(* Logix 5000 project; controller Motion_Axis_AOIs_AMCI_RSLogix_V31 vendor 1 type 14 code 108 rev 31.11; software revision 31.02; part 3 of 7 *)

ADD_ON_INSTRUCTION AMCI_MA_SD_SMD_Linear_Follower   (* revision 5.0, vendor AMCI, ExecuteEnableInFalse *)
// Linear Axis Follower for SD and SMD devices.   Will not work with SV integrated servo devices.
// Help:
// MOTION AXIS SD & SMD LINEAR FOLLOWER
// These AOIs will only work with the SD and SMD motion devices.  The SV motion devices have their own follower AOIs.
// AXIS INPUT DATA:  Input data from AMCI motion device.   Uses the AMCI_Motion_Axis_Input_Data User Defined Data Type.
// AXIS OUTPUT DATA; Output data from the AOI to the AMCI motion device.   Uses the AMCI_Motion_Axis_Output_Data User Defined Data Type.
// FOLLOWER POSITION: REAL DATA TYPE position directly from the motion axis.
// FOLLOWER VELOCITY: REAL DATA TYPE velocity directly from the motion axis.
// ACCELERATION & DECELERATION: An actual value or an INT DATA TYPE.  Larger acceleration and
//                                                             deceleration values will cause the motion device to more quickly react
//                                                              changes in the source position and velocity values.
// PROPORTIONAL COEFFICIENT:  A value of 1 or 2 is recommended
// NETWORK DELAY: A value of zero, or 1 to the RPI time, will work in most applications.
// EN (Enable) Set when rung is true, Reset when rung is false
// DN (Done) Set when command is sent to the motion device.  Reset when the rung is false.
// ER (Error) Set when a command or input error failed to clear.  Reset when the rung is false.
// IP (In Process) Set when follower command is active, even if motion is not occurring.   Reset when the rung
//                         goes false.
VAR_IN_OUT
   Axis_Input_Data : AMCI_Motion_Axis_Input_Data; {required}
   Axis_Output_Data : AMCI_Motion_Axis_Output_Data; {required}
END_VAR
VAR_INPUT
   _0_for_Normal_1_for_Continuous : BOOL;
   Follower_Position : REAL; {required}
   Follower_Velocity : REAL; {required}
   Acceleration : INT; {required}
   Deceleration : INT; {required}
   Proportional_Coefficient : INT; {required}
   Network_delay : INT; {required}
END_VAR
VAR_OUTPUT
   EN : BOOL; {visible}
   ER : BOOL; {visible}
   DN : BOOL; {visible}
   IP : BOOL; {visible}
END_VAR
VAR
   command_data_block : INT[10];
        [2]   // Upper Target Position
        [4]   // Upper Programmed Speed
        [1]   // Command Bits LSW
        [5]   // Lower Programmed Speed
        [0]   // Command Bits MSW
        [3]   // Lower Target Position
   axis_follower_position : DINT;
   axis_follower_velocity : DINT;
END_VAR

ROUTINE EnableInFalse   (* ladder *)
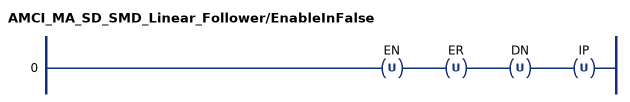
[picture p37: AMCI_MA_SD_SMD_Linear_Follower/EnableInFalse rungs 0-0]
   0: OTU(EN)OTU(ER)OTU(DN)OTU(IP);
END_ROUTINE

ROUTINE Logic   (* ladder *)
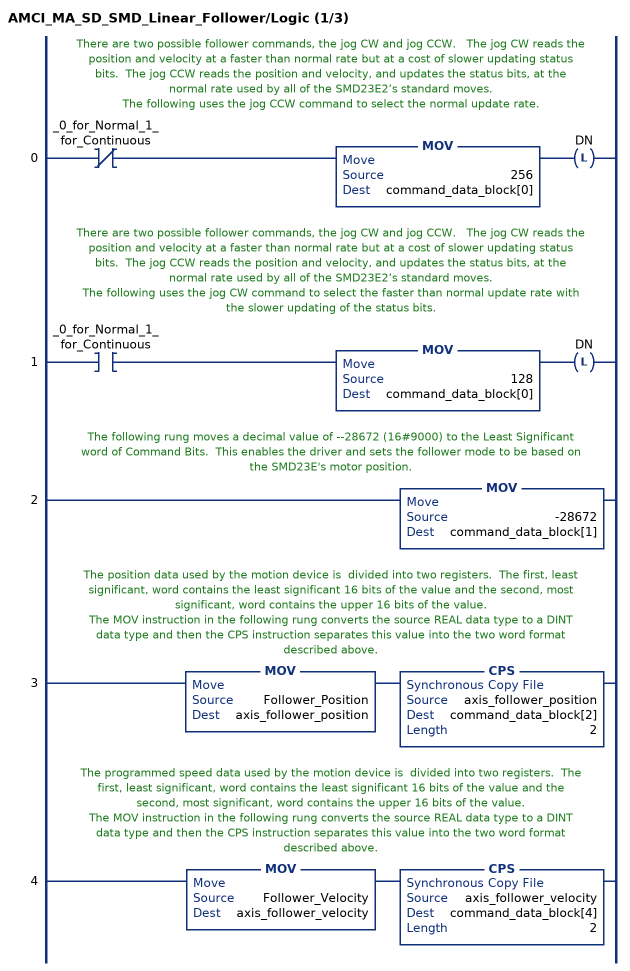
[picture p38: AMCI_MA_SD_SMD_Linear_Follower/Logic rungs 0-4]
   // There are two possible follower commands, the jog CW and jog CCW.   The jog CW reads the position and velocity at a faster than normal rate but at a cost of slower updating status bits.  The jog CCW reads the position and velocity, and updates the status bits, at the normal rate used by all of the SMD23E2’s standard moves.
   // The following uses the jog CCW command to select the normal update rate.
   0: XIO(_0_for_Normal_1_for_Continuous)MOV(256,command_data_block[0])OTL(DN);
   // There are two possible follower commands, the jog CW and jog CCW.   The jog CW reads the position and velocity at a faster than normal rate but at a cost of slower updating status bits.  The jog CCW reads the position and velocity, and updates the status bits, at the normal rate used by all of the SMD23E2’s standard moves.
   // The following uses the jog CW command to select the faster than normal update rate with the slower updating of the status bits.
   1: XIC(_0_for_Normal_1_for_Continuous)MOV(128,command_data_block[0])OTL(DN);
   // The following rung moves a decimal value of --28672 (16#9000) to the Least Significant word of Command Bits.  This enables the driver and sets the follower mode to be based on the SMD23E's motor position.
   2: MOV(-28672,command_data_block[1]);
   // The position data used by the motion device is  divided into two registers.  The first, least significant, word contains the least significant 16 bits of the value and the second, most significant, word contains the upper 16 bits of the value.
   // The MOV instruction in the following rung converts the source REAL data type to a DINT data type and then the CPS instruction separates this value into the two word format described above.
   3: MOV(Follower_Position,axis_follower_position)CPS(axis_follower_position,command_data_block[2],2);
   // The programmed speed data used by the motion device is  divided into two registers.  The first, least significant, word contains the least significant 16 bits of the value and the second, most significant, word contains the upper 16 bits of the value.
   // The MOV instruction in the following rung converts the source REAL data type to a DINT data type and then the CPS instruction separates this value into the two word format described above.
   4: MOV(Follower_Velocity,axis_follower_velocity)CPS(axis_follower_velocity,command_data_block[4],2);
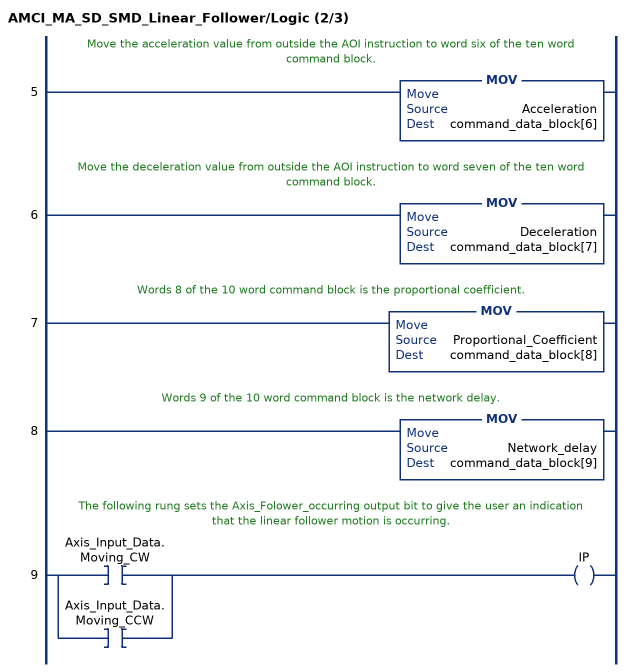
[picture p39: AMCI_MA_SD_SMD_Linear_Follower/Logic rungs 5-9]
   // Move the acceleration value from outside the AOI instruction to word six of the ten word command block.
   5: MOV(Acceleration,command_data_block[6]);
   // Move the deceleration value from outside the AOI instruction to word seven of the ten word command block.
   6: MOV(Deceleration,command_data_block[7]);
   // Words 8 of the 10 word command block is the proportional coefficient.
   7: MOV(Proportional_Coefficient,command_data_block[8]);
   // Words 9 of the 10 word command block is the network delay.
   8: MOV(Network_delay,command_data_block[9]);
   // The following rung sets the Axis_Folower_occurring output bit to give the user an indication that the linear follower motion is occurring.
   9: [XIC(Axis_Input_Data.Moving_CW) ,XIC(Axis_Input_Data.Moving_CCW) ]OTE(IP);
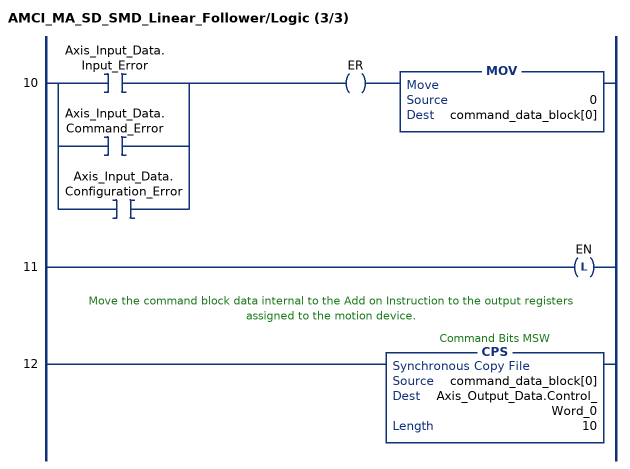
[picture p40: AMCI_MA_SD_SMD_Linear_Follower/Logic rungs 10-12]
   10: [XIC(Axis_Input_Data.Input_Error) ,XIC(Axis_Input_Data.Command_Error) ,XIC(Axis_Input_Data.Configuration_Error) ]OTE(ER)MOV(0,command_data_block[0]);
   11: OTL(EN);
   // Move the command block data internal to the Add on Instruction to the output registers assigned to the motion device.
   12: CPS(command_data_block[0],Axis_Output_Data.Control_Word_0,10);
END_ROUTINE
END_ADD_ON_INSTRUCTION

ADD_ON_INSTRUCTION AMCI_MA_SD_SMD_Linear_Follower_CIPSYNC   (* revision 1.0, vendor AMCI, ExecuteEnableInFalse *)
// Linear Axis Follower for SD and SMD devices.   Will not work with SV integrated servo devices.
// Revision note:
// 8/8/24.  Added timesync functionality to a previously existing AOI.  Also added logic to preset the motor position to the master axis position when the rung with the AOI becomes true, or if the master axis position changes when motion is not occurring.
// Help:
// MOTION AXIS SD & SMD LINEAR FOLLOWER
// These AOIs will only work with the SD and SMD motion devices.  The SV motion devices have their own follower AOIs.
// AXIS INPUT DATA:  Input data from AMCI motion device.   Uses the AMCI_Motion_Axis_Input_Data User Defined Data Type.
// AXIS OUTPUT DATA; Output data from the AOI to the AMCI motion device.   Uses the AMCI_Motion_Axis_Output_Data User Defined Data Type.
// FOLLOWER POSITION: REAL DATA TYPE position directly from the motion axis.
// FOLLOWER VELOCITY: REAL DATA TYPE velocity directly from the motion axis.
// ACCELERATION & DECELERATION: An actual value or an INT DATA TYPE.  Larger acceleration and
//                                                             deceleration values will cause the motion device to more quickly react
//                                                              changes in the source position and velocity values.
// PROPORTIONAL COEFFICIENT:  A value of 1 or 2 is recommended
// NETWORK DELAY: A value of zero, or 1 to the RPI time, will work in most applications.
// RPI_TIME: The RPI time used when adding the AMCI Motion device to the network.   8ms is the default.
//                    Used to control how long the preset motor command is sent to the device when the rung with the
//                    AOI transitions from false to true.
// TIMESYNC: The PLC's time value used to more closely synchronize the motion data from the PLC's master
//                     axis with the output of the AMCI motion device.
// EN (Enable) Set when rung is true, Reset when rung is false
// DN (Done) Set when command is sent to the motion device.  Reset when the rung is false.
// ER (Error) Set when a command or input error failed to clear.  Reset when the rung is false.
// IP (In Process) Set when follower command is active, even if motion is not occurring.   Reset when the rung
//                         goes false.
VAR_IN_OUT
   Axis_Input_Data : AMCI_Motion_Axis_Input_Data; {required}
   Axis_Output_Data : AMCI_Motion_Axis_Output_Data; {required}
END_VAR
VAR_INPUT
   Current_System_Time : DINT; {required}
   _0_for_Normal_1_for_Continuous : BOOL;
   Master_Axis_Position : REAL; {required}
   Master_Axis_Velocity : REAL; {required}
   Acceleration : INT; {required}
   Deceleration : INT; {required}
   Proportional_Coefficient : INT; {required}
   RPI_time_in_ms : DINT; {required}
END_VAR
VAR_OUTPUT
   EN : BOOL; {visible}
   ER : BOOL; {visible}
   DN : BOOL; {visible}
   IP : BOOL; {visible}
END_VAR
VAR
   command_data_block : INT[10];
        [1]   // Command Bits LSW
        [3]   // Lower Target Position
        [5]   // Lower Programmed Speed
        [0]   // Command Bits MSW
        [2]   // Upper Target Position
        [4]   // Upper Programmed Speed
   axis_follower_position : DINT;
   axis_follower_velocity : DINT;
   Preset_Motor_Position_timer_dynanic : TIMER; {access None}
   preset_one_shot : BOOL; {access None}
   RPI_div_1000 : REAL; {access None}
   difference_scan_position : DINT; {access None}
   last_scan_position : DINT; {access None}
   position_difference : DINT; {access None}
   position_last_scan_linear_SMD : DINT; {access None}
END_VAR

ROUTINE EnableInFalse   (* ladder *)
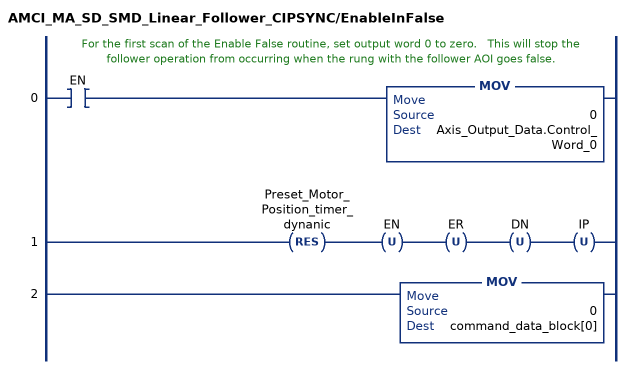
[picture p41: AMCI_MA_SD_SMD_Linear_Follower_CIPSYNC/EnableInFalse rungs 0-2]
   // For the first scan of the Enable False routine, set output word 0 to zero.   This will stop the follower operation from occurring when the rung with the follower AOI goes false.
   0: XIC(EN)MOV(0,Axis_Output_Data.Control_Word_0);
   1: RES(Preset_Motor_Position_timer_dynanic)OTU(EN)OTU(ER)OTU(DN)OTU(IP);
   2: MOV(0,command_data_block[0]);
END_ROUTINE

ROUTINE Logic   (* ladder *)
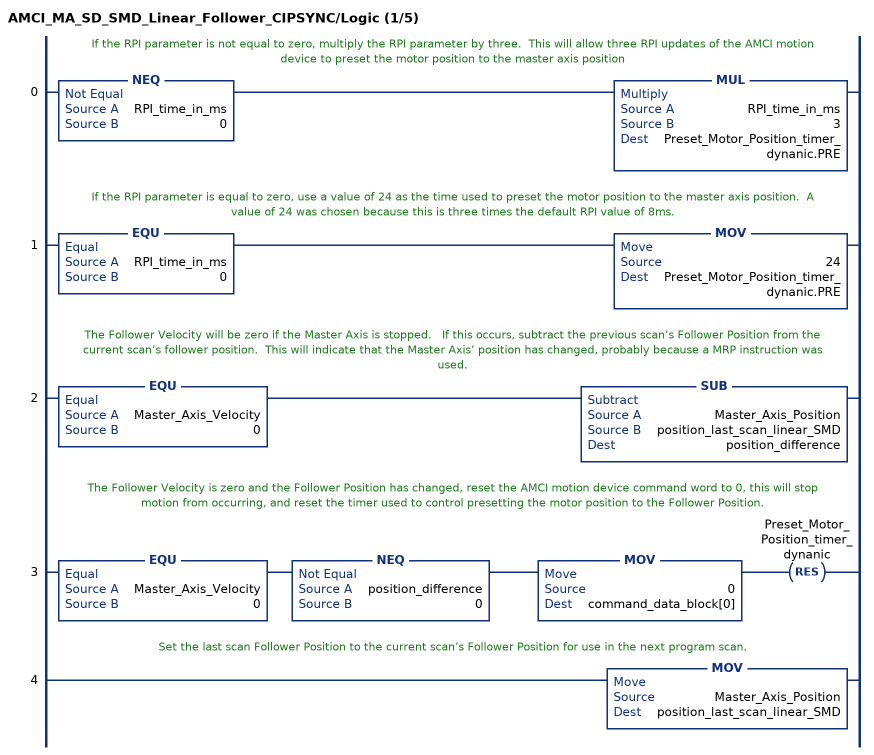
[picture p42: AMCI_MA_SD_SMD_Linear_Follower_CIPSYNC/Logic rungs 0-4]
   // If the RPI parameter is not equal to zero, multiply the RPI parameter by three.  This will allow three RPI updates of the AMCI motion device to preset the motor position to the master axis position
   0: NEQ(RPI_time_in_ms,0)MUL(RPI_time_in_ms,3,Preset_Motor_Position_timer_dynanic.PRE);
   // If the RPI parameter is equal to zero, use a value of 24 as the time used to preset the motor position to the master axis position.  A value of 24 was chosen because this is three times the default RPI value of 8ms.
   1: EQU(RPI_time_in_ms,0)MOV(24,Preset_Motor_Position_timer_dynanic.PRE);
   // The Follower Velocity will be zero if the Master Axis is stopped.   If this occurs, subtract the previous scan’s Follower Position from the current scan’s follower position.  This will indicate that the Master Axis’ position has changed, probably because a MRP instruction was used.
   2: EQU(Master_Axis_Velocity,0)SUB(Master_Axis_Position,position_last_scan_linear_SMD,position_difference);
   // The Follower Velocity is zero and the Follower Position has changed, reset the AMCI motion device command word to 0, this will stop motion from occurring, and reset the timer used to control presetting the motor position to the Follower Position.
   3: EQU(Master_Axis_Velocity,0)NEQ(position_difference,0)MOV(0,command_data_block[0])RES(Preset_Motor_Position_timer_dynanic);
   // Set the last scan Follower Position to the current scan’s Follower Position for use in the next program scan.
   4: MOV(Master_Axis_Position,position_last_scan_linear_SMD);
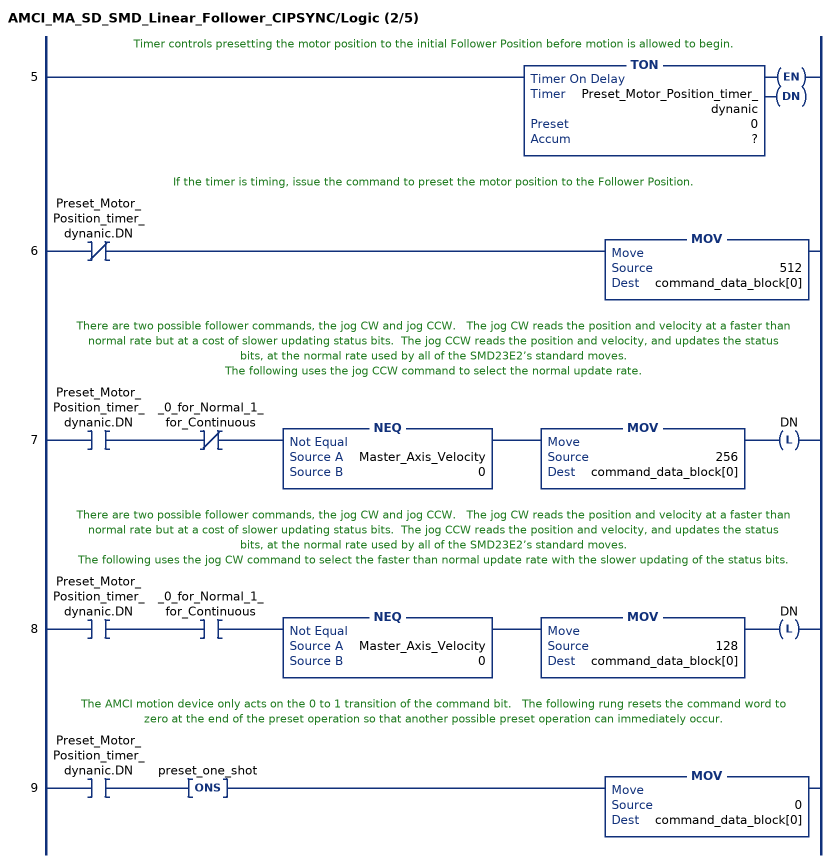
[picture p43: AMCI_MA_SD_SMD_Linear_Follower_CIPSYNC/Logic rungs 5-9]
   // Timer controls presetting the motor position to the initial Follower Position before motion is allowed to begin.
   5: TON(Preset_Motor_Position_timer_dynanic,?,?);
   // If the timer is timing, issue the command to preset the motor position to the Follower Position.
   6: XIO(Preset_Motor_Position_timer_dynanic.DN)MOV(512,command_data_block[0]);
   // There are two possible follower commands, the jog CW and jog CCW.   The jog CW reads the position and velocity at a faster than normal rate but at a cost of slower updating status bits.  The jog CCW reads the position and velocity, and updates the status bits, at the normal rate used by all of the SMD23E2’s standard moves.
   // The following uses the jog CCW command to select the normal update rate.
   7: XIC(Preset_Motor_Position_timer_dynanic.DN)XIO(_0_for_Normal_1_for_Continuous)NEQ(Master_Axis_Velocity,0)MOV(256,command_data_block[0])OTL(DN);
   // There are two possible follower commands, the jog CW and jog CCW.   The jog CW reads the position and velocity at a faster than normal rate but at a cost of slower updating status bits.  The jog CCW reads the position and velocity, and updates the status bits, at the normal rate used by all of the SMD23E2’s standard moves.
   // The following uses the jog CW command to select the faster than normal update rate with the slower updating of the status bits.
   8: XIC(Preset_Motor_Position_timer_dynanic.DN)XIC(_0_for_Normal_1_for_Continuous)NEQ(Master_Axis_Velocity,0)MOV(128,command_data_block[0])OTL(DN);
   // The AMCI motion device only acts on the 0 to 1 transition of the command bit.   The following rung resets the command word to zero at the end of the preset operation so that another possible preset operation can immediately occur.
   9: XIC(Preset_Motor_Position_timer_dynanic.DN)ONS(preset_one_shot)MOV(0,command_data_block[0]);
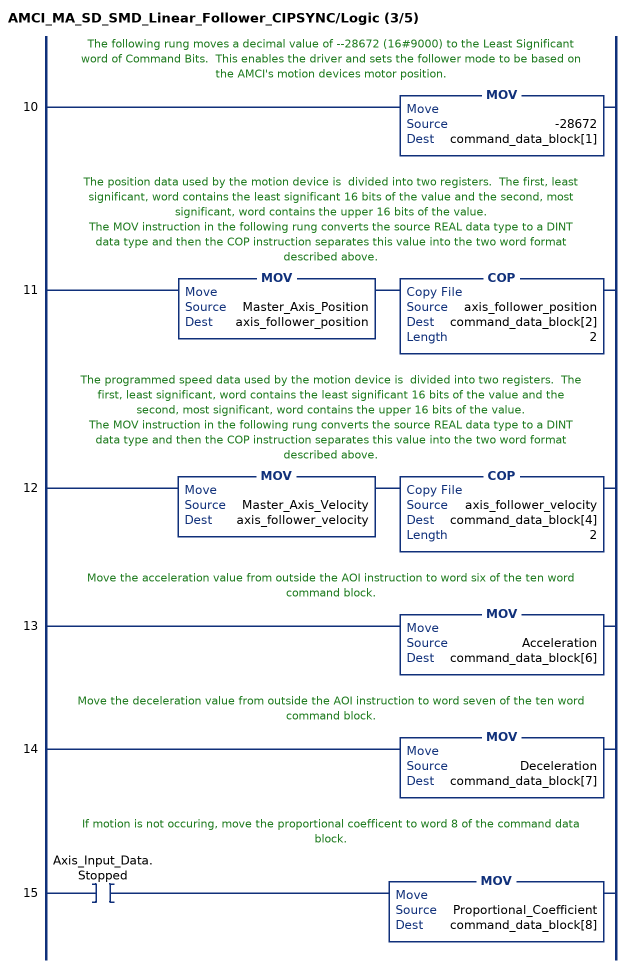
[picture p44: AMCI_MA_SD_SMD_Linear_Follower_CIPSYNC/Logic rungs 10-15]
   // The following rung moves a decimal value of --28672 (16#9000) to the Least Significant word of Command Bits.  This enables the driver and sets the follower mode to be based on the AMCI's motion devices motor position.
   10: MOV(-28672,command_data_block[1]);
   // The position data used by the motion device is  divided into two registers.  The first, least significant, word contains the least significant 16 bits of the value and the second, most significant, word contains the upper 16 bits of the value.
   // The MOV instruction in the following rung converts the source REAL data type to a DINT data type and then the COP instruction separates this value into the two word format described above.
   11: MOV(Master_Axis_Position,axis_follower_position)COP(axis_follower_position,command_data_block[2],2);
   // The programmed speed data used by the motion device is  divided into two registers.  The first, least significant, word contains the least significant 16 bits of the value and the second, most significant, word contains the upper 16 bits of the value.
   // The MOV instruction in the following rung converts the source REAL data type to a DINT data type and then the COP instruction separates this value into the two word format described above.
   12: MOV(Master_Axis_Velocity,axis_follower_velocity)COP(axis_follower_velocity,command_data_block[4],2);
   // Move the acceleration value from outside the AOI instruction to word six of the ten word command block.
   13: MOV(Acceleration,command_data_block[6]);
   // Move the deceleration value from outside the AOI instruction to word seven of the ten word command block.
   14: MOV(Deceleration,command_data_block[7]);
   // If motion is not occuring, move the proportional coefficent to word 8 of the command data block.
   15: XIC(Axis_Input_Data.Stopped)MOV(Proportional_Coefficient,command_data_block[8]);
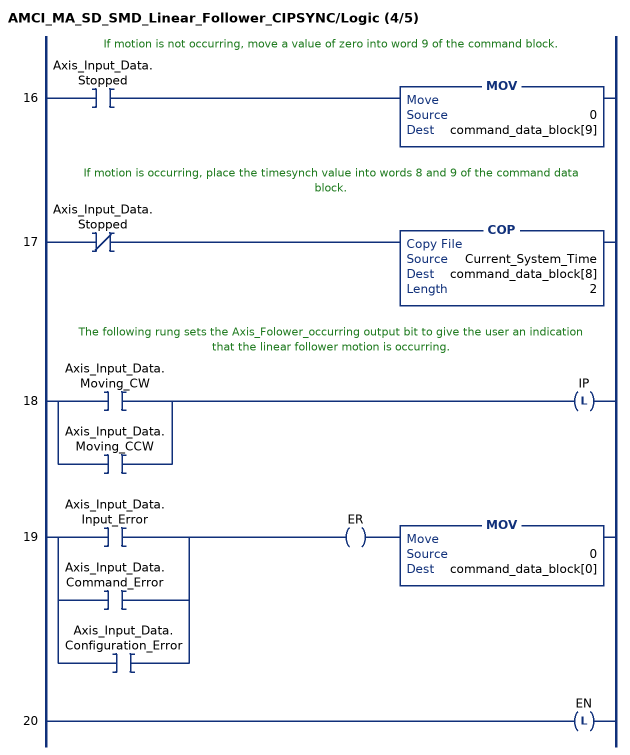
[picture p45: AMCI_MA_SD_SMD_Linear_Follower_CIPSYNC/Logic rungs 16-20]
   // If motion is not occurring, move a value of zero into word 9 of the command block.
   16: XIC(Axis_Input_Data.Stopped)MOV(0,command_data_block[9]);
   // If motion is occurring, place the timesynch value into words 8 and 9 of the command data block.
   17: XIO(Axis_Input_Data.Stopped)COP(Current_System_Time,command_data_block[8],2);
   // The following rung sets the Axis_Folower_occurring output bit to give the user an indication that the linear follower motion is occurring.
   18: [XIC(Axis_Input_Data.Moving_CW) ,XIC(Axis_Input_Data.Moving_CCW) ]OTL(IP);
   19: [XIC(Axis_Input_Data.Input_Error) ,XIC(Axis_Input_Data.Command_Error) ,XIC(Axis_Input_Data.Configuration_Error) ]OTE(ER)MOV(0,command_data_block[0]);
   20: OTL(EN);
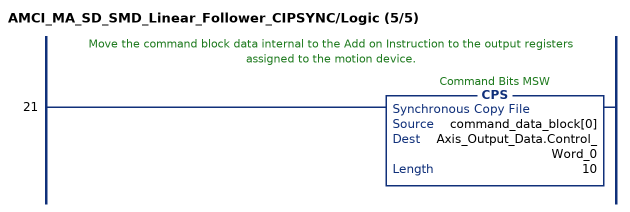
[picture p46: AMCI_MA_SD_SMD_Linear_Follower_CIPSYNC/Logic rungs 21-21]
   // Move the command block data internal to the Add on Instruction to the output registers assigned to the motion device.
   21: CPS(command_data_block[0],Axis_Output_Data.Control_Word_0,10);
END_ROUTINE
END_ADD_ON_INSTRUCTION

ADD_ON_INSTRUCTION AMCI_MA_SV_Circular_Follower   (* revision 1.1, vendor AMCI, ExecuteEnableInFalse *)
// Only for SVXXXE2 motion devices.
// Revision note:
// Version 1.1:  Corrected mistake in the text on the Help Tab.   Also limited the velocity to +/-1,048,575 steps / sec.
// Help:
// MOTION AXIS SV CIRCULAR FOLLOWER
// These AOIs will only work with the SV motion devices.  The SMD and SD  motion devices have their own follower AOIs.
// AXIS INPUT DATA:  Input data from AMCI motion device.   Uses the AMCI_Motion_Axis_Input_Data User Defined Data Type.
// AXIS OUTPUT DATA; Output data from the AOI to the AMCI motion device.   Uses the AMCI_Motion_Axis_Output_Data User Defined Data Type.
// FOLLOWER POSITION: REAL DATA TYPE position directly from the motion axis.
// FOLLOWER VELOCITY: REAL DATA TYPE velocity directly from the motion axis.
// FOLLOWER ACCELERATION: REAL DATA TYPE acceleration directly from the motion axis.
// RAMP ACCELERATION: An actual value or INT value used to transition from no motion to motion.   Once
//                                          motion is occurring, the follower acceleration will be used.  Range of 0 to 15,999.
// DECELERATION: An actual value or INT value used to transition from motion to no motion.   Range of 0 to
//                              15,999.
// CONVERSION CONSTANT: Converts revolutions and revolutions / sec  from the motion axis to the step and
//                                               steps / sec used by the motion axis.
// POSITION UNWIND: Must be set to the Unwind Value of the motion axis and defines the point at which the
//                                    position data will transition from its maximum to its minimum value.    The Position
//                                    Unwind Value MUST BE IN THE RANGE OF 21 TO 65535.
// EN (Enable) Set when rung is true, Reset when rung is false
// DN (Done) Set when command is sent to the motion device.  Reset when the rung is false.
// ER (Error) Set when a command or input error failed to clear.  Reset when the rung is false.
// IP (In Process) Set when motion is occurring.   Reset when the rung goes false.
VAR_IN_OUT
   Axis_Input_Data : AMCI_Motion_Axis_Input_Data; {required}
   Axis_Output_Data : AMCI_Motion_Axis_Output_Data; {required}
END_VAR
VAR_INPUT
   Follower_Position : REAL; {required}
   Follower_Velocity : REAL; {required}
   Follower_Acceleration : REAL; {required}
   Ramp_Acceleration : INT; {required}
   Deceleration : INT; {required}
   Conversion_Constant : REAL; {required}
   Position_Unwind : DINT; {required}
   Maximum_Move_Torque : INT;
END_VAR
VAR_OUTPUT
   EN : BOOL; {visible}
   ER : BOOL; {visible}
   DN : BOOL; {access Read Only, visible}
   IP : BOOL; {access Read Only, visible}
END_VAR
VAR
   command_data_block : INT[10];
        [8]   // Unwind value when stopped, Maximum Move Torque when motion occurring
        [2]   // Upper Target Position
        [4]   // Upper Programmed Speed
        [1]   // Command Bits LSW
        [3]   // Lower Target Position
        [5]   // Lower Programmed Speed
        [0]   // Command Bits MSW
   axis_follower_position : DINT;
   axis_follower_velocity : DINT;
   axis_follower_acceleration : DINT; {access None}
END_VAR

ROUTINE EnableInFalse   (* ladder *)
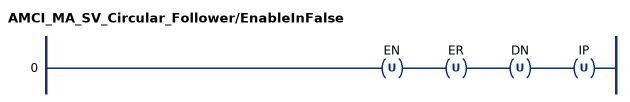
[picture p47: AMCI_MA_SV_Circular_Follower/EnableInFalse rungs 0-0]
   0: OTU(EN)OTU(ER)OTU(DN)OTU(IP);
END_ROUTINE

ROUTINE Logic   (* ladder *)
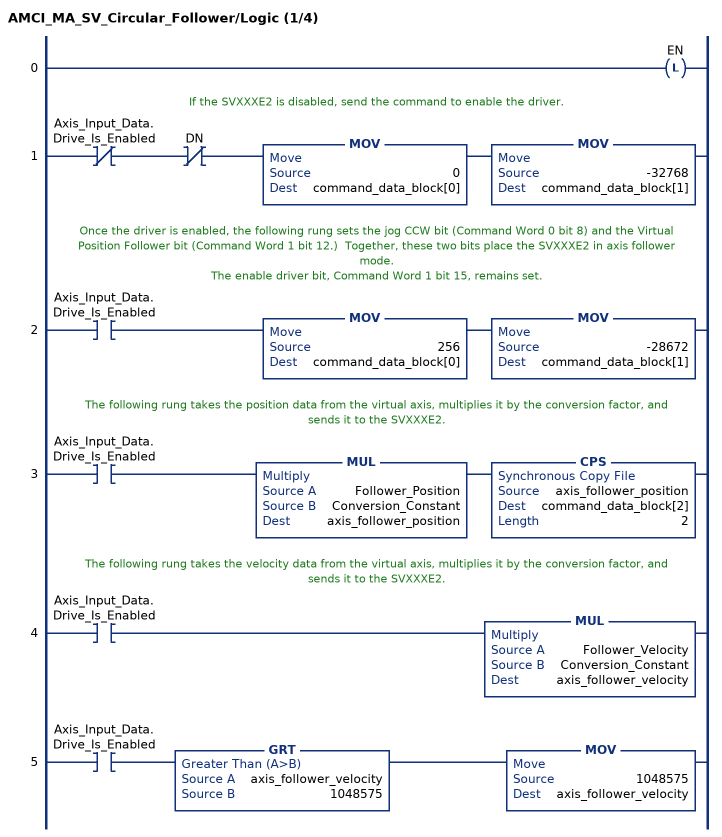
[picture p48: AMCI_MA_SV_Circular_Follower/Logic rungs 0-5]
   0: OTL(EN);
   // If the SVXXXE2 is disabled, send the command to enable the driver.
   1: XIO(Axis_Input_Data.Drive_Is_Enabled)XIO(DN)MOV(0,command_data_block[0])MOV(-32768,command_data_block[1]);
   // Once the driver is enabled, the following rung sets the jog CCW bit (Command Word 0 bit 8) and the Virtual Position Follower bit (Command Word 1 bit 12.)  Together, these two bits place the SVXXXE2 in axis follower mode.
   // The enable driver bit, Command Word 1 bit 15, remains set.
   2: XIC(Axis_Input_Data.Drive_Is_Enabled)MOV(256,command_data_block[0])MOV(-28672,command_data_block[1]);
   // The following rung takes the position data from the virtual axis, multiplies it by the conversion factor, and sends it to the SVXXXE2.
   3: XIC(Axis_Input_Data.Drive_Is_Enabled)MUL(Follower_Position,Conversion_Constant,axis_follower_position)CPS(axis_follower_position,command_data_block[2],2);
   // The following rung takes the velocity data from the virtual axis, multiplies it by the conversion factor, and sends it to the SVXXXE2.
   4: XIC(Axis_Input_Data.Drive_Is_Enabled)MUL(Follower_Velocity,Conversion_Constant,axis_follower_velocity);
   5: XIC(Axis_Input_Data.Drive_Is_Enabled)GRT(axis_follower_velocity,1048575)MOV(1048575,axis_follower_velocity);
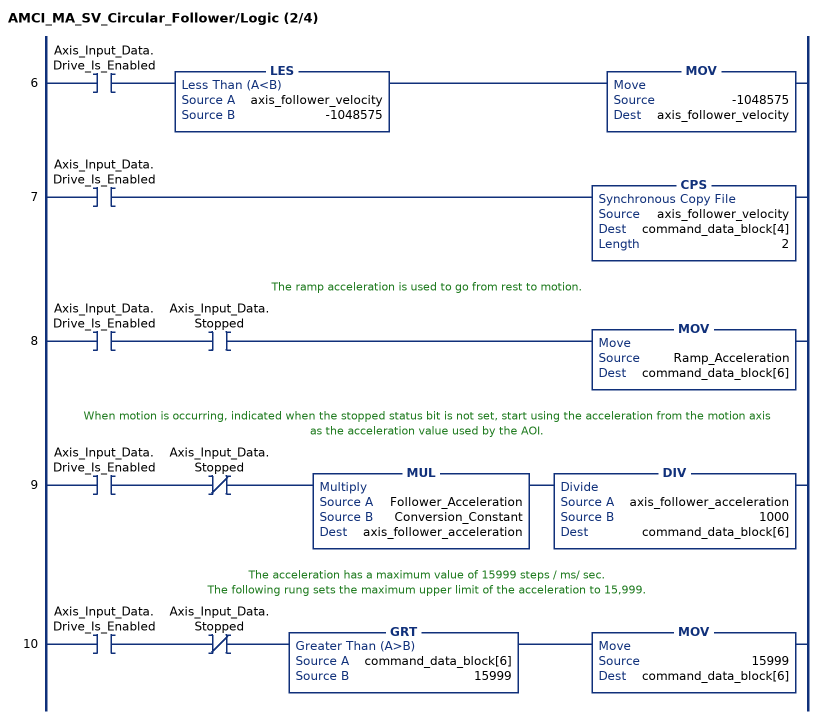
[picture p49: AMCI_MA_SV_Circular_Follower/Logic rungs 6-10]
   6: XIC(Axis_Input_Data.Drive_Is_Enabled)LES(axis_follower_velocity,-1048575)MOV(-1048575,axis_follower_velocity);
   7: XIC(Axis_Input_Data.Drive_Is_Enabled)CPS(axis_follower_velocity,command_data_block[4],2);
   // The ramp acceleration is used to go from rest to motion.
   8: XIC(Axis_Input_Data.Drive_Is_Enabled)XIC(Axis_Input_Data.Stopped)MOV(Ramp_Acceleration,command_data_block[6]);
   // When motion is occurring, indicated when the stopped status bit is not set, start using the acceleration from the motion axis as the acceleration value used by the AOI.
   9: XIC(Axis_Input_Data.Drive_Is_Enabled)XIO(Axis_Input_Data.Stopped)MUL(Follower_Acceleration,Conversion_Constant,axis_follower_acceleration)DIV(axis_follower_acceleration,1000,command_data_block[6]);
   // The acceleration has a maximum value of 15999 steps / ms/ sec.
   // The following rung sets the maximum upper limit of the acceleration to 15,999.
   10: XIC(Axis_Input_Data.Drive_Is_Enabled)XIO(Axis_Input_Data.Stopped)GRT(command_data_block[6],15999)MOV(15999,command_data_block[6]);
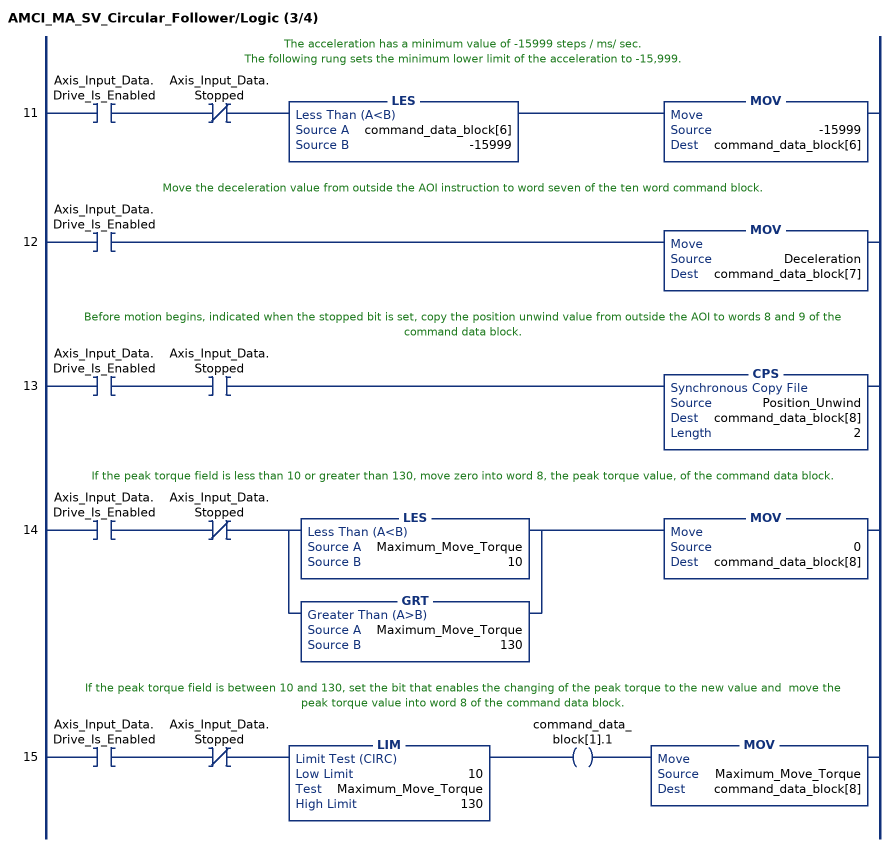
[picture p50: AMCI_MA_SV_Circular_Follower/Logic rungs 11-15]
   // The acceleration has a minimum value of -15999 steps / ms/ sec.
   // The following rung sets the minimum lower limit of the acceleration to -15,999.
   11: XIC(Axis_Input_Data.Drive_Is_Enabled)XIO(Axis_Input_Data.Stopped)LES(command_data_block[6],-15999)MOV(-15999,command_data_block[6]);
   // Move the deceleration value from outside the AOI instruction to word seven of the ten word command block.
   12: XIC(Axis_Input_Data.Drive_Is_Enabled)MOV(Deceleration,command_data_block[7]);
   // Before motion begins, indicated when the stopped bit is set, copy the position unwind value from outside the AOI to words 8 and 9 of the command data block.
   13: XIC(Axis_Input_Data.Drive_Is_Enabled)XIC(Axis_Input_Data.Stopped)CPS(Position_Unwind,command_data_block[8],2);
   // If the peak torque field is less than 10 or greater than 130, move zero into word 8, the peak torque value, of the command data block.
   14: XIC(Axis_Input_Data.Drive_Is_Enabled)XIO(Axis_Input_Data.Stopped)[LES(Maximum_Move_Torque,10) ,GRT(Maximum_Move_Torque,130) ]MOV(0,command_data_block[8]);
   // If the peak torque field is between 10 and 130, set the bit that enables the changing of the peak torque to the new value and  move the peak torque value into word 8 of the command data block.
   15: XIC(Axis_Input_Data.Drive_Is_Enabled)XIO(Axis_Input_Data.Stopped)LIM(10,Maximum_Move_Torque,130)OTE(command_data_block[1].1)MOV(Maximum_Move_Torque,command_data_block[8]);
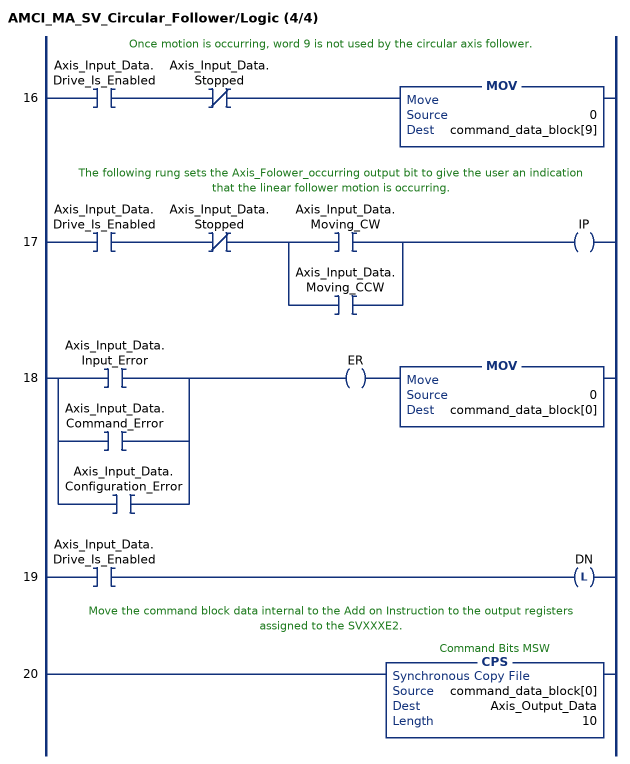
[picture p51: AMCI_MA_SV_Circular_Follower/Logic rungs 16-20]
   // Once motion is occurring, word 9 is not used by the circular axis follower.
   16: XIC(Axis_Input_Data.Drive_Is_Enabled)XIO(Axis_Input_Data.Stopped)MOV(0,command_data_block[9]);
   // The following rung sets the Axis_Folower_occurring output bit to give the user an indication that the linear follower motion is occurring.
   17: XIC(Axis_Input_Data.Drive_Is_Enabled)XIO(Axis_Input_Data.Stopped)[XIC(Axis_Input_Data.Moving_CW) ,XIC(Axis_Input_Data.Moving_CCW) ]OTE(IP);
   18: [XIC(Axis_Input_Data.Input_Error) ,XIC(Axis_Input_Data.Command_Error) ,XIC(Axis_Input_Data.Configuration_Error) ]OTE(ER)MOV(0,command_data_block[0]);
   19: XIC(Axis_Input_Data.Drive_Is_Enabled)OTL(DN);
   // Move the command block data internal to the Add on Instruction to the output registers assigned to the SVXXXE2.
   20: CPS(command_data_block[0],Axis_Output_Data,10);
END_ROUTINE
END_ADD_ON_INSTRUCTION

ADD_ON_INSTRUCTION AMCI_MA_SV_Circular_Follower_CIPSync   (* revision 1.0, vendor AMCI, ExecuteEnableInFalse *)
// Only for SVXXXE2 motion devices.
// Revision note:
// 8/8/24.  Added CIPSync functionality to a previously existing AOI.  The abiltiy to change the maximum move torque is no longer available because the time value uses the same output words as the torque value.
// Help:
// MOTION AXIS SV CIRCULAR FOLLOWER
// These AOIs will only work with the SD and SMD motion devices.  The SV motion devices have their own follower AOIs.
// AXIS INPUT DATA:  Input data from AMCI motion device.   Uses the AMCI_Motion_Axis_Input_Data User Defined Data Type.
// AXIS OUTPUT DATA; Output data from the AOI to the AMCI motion device.   Uses the AMCI_Motion_Axis_Output_Data User Defined Data Type.
// FOLLOWER POSITION: REAL DATA TYPE position directly from the motion axis.
// FOLLOWER VELOCITY: REAL DATA TYPE velocity directly from the motion axis.
// FOLLOWER ACCELERATION: REAL DATA TYPE acceleration directly from the motion axis.
// RAMP ACCELERATION: An actual value or INT value used to transition from no motion to motion.   Once
//                                          motion is occurring, the follower acceleration will be used.  Range of 0 to 15,999.
// DECELERATION: An actual value or INT value used to transition from motion to no motion.   Range of 0 to
//                              15,999.
// CONVERSION CONSTANT: Converts revolutions and revolutions / sec  from the motion axis to the step and
//                                               steps / sec used by the motion axis.
// POSITION UNWIND: Must be set to the Unwind Value of the motion axis and defines the point at which the
//                                    position data will transition from its maximum to its minimum value.    The Position
//                                    Unwind Value MUST BE IN THE RANGE OF 21 TO 65535.
// EN (Enable) Set when rung is true, Reset when rung is false
// DN (Done) Set when command is sent to the motion device.  Reset when the rung is false.
// ER (Error) Set when a command or input error failed to clear.  Reset when the rung is false.
// IP (In Process) Set when motion is occurring.   Reset when the rung goes false.
VAR_IN_OUT
   Axis_Input_Data : AMCI_Motion_Axis_Input_Data; {required}
   Axis_Output_Data : AMCI_Motion_Axis_Output_Data; {required}
END_VAR
VAR_INPUT
   current_system_time : DINT; {required}
   Master_Axis_Position : REAL; {required}
   Master_Axis_Velocity : REAL; {required}
   Master_Acceleration : REAL; {required}
   Ramp_Acceleration : INT; {required}
   Deceleration : INT; {required}
   Conversion_Constant : REAL; {required}
   Position_Unwind : DINT; {required}
END_VAR
VAR_OUTPUT
   EN : BOOL; {visible}
   ER : BOOL; {visible}
   DN : BOOL; {access Read Only, visible}
   IP : BOOL; {access Read Only, visible}
END_VAR
VAR
   command_data_block : INT[10];
        [8]   // Unwind value when stopped, Maximum Move Torque when motion occurring
        [2]   // Upper Target Position
        [4]   // Upper Programmed Speed
        [5]   // Lower Programmed Speed
        [0]   // Command Bits MSW
        [1]   // Command Bits LSW
        [3]   // Lower Target Position
   axis_follower_position : DINT;
   axis_follower_velocity : DINT;
   axis_follower_acceleration : DINT; {access None}
END_VAR

ROUTINE EnableInFalse   (* ladder *)
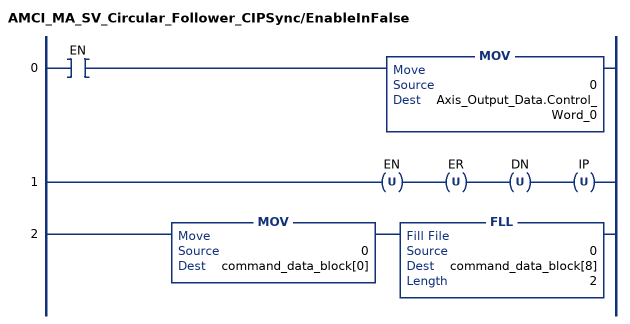
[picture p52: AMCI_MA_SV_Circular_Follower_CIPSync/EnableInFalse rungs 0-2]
   0: XIC(EN)MOV(0,Axis_Output_Data.Control_Word_0);
   1: OTU(EN)OTU(ER)OTU(DN)OTU(IP);
   2: MOV(0,command_data_block[0])FLL(0,command_data_block[8],2);
END_ROUTINE

ROUTINE Logic   (* ladder *)
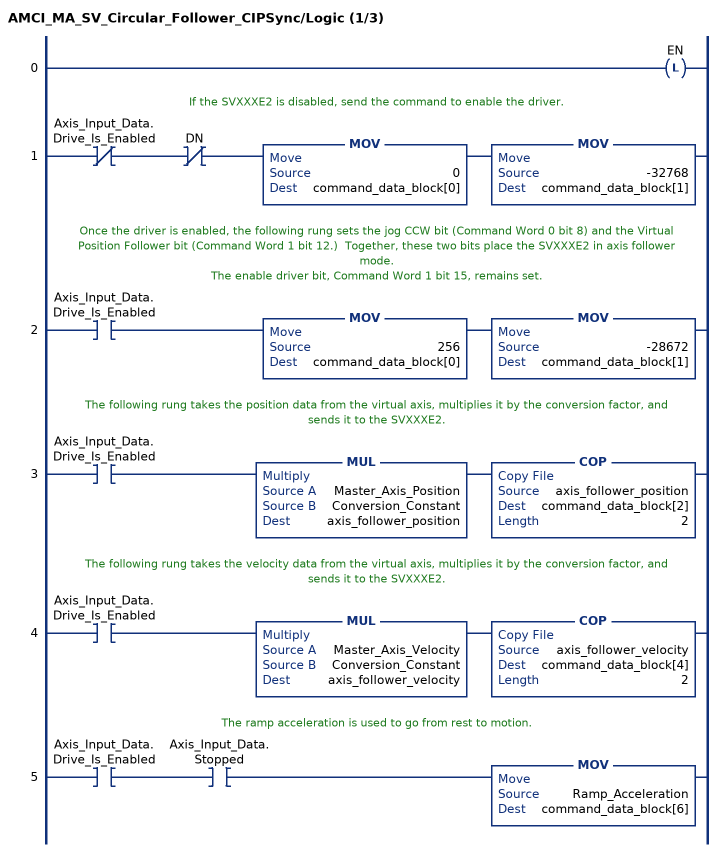
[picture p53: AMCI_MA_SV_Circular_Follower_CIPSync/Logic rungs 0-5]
   0: OTL(EN);
   // If the SVXXXE2 is disabled, send the command to enable the driver.
   1: XIO(Axis_Input_Data.Drive_Is_Enabled)XIO(DN)MOV(0,command_data_block[0])MOV(-32768,command_data_block[1]);
   // Once the driver is enabled, the following rung sets the jog CCW bit (Command Word 0 bit 8) and the Virtual Position Follower bit (Command Word 1 bit 12.)  Together, these two bits place the SVXXXE2 in axis follower mode.
   // The enable driver bit, Command Word 1 bit 15, remains set.
   2: XIC(Axis_Input_Data.Drive_Is_Enabled)MOV(256,command_data_block[0])MOV(-28672,command_data_block[1]);
   // The following rung takes the position data from the virtual axis, multiplies it by the conversion factor, and sends it to the SVXXXE2.
   3: XIC(Axis_Input_Data.Drive_Is_Enabled)MUL(Master_Axis_Position,Conversion_Constant,axis_follower_position)COP(axis_follower_position,command_data_block[2],2);
   // The following rung takes the velocity data from the virtual axis, multiplies it by the conversion factor, and sends it to the SVXXXE2.
   4: XIC(Axis_Input_Data.Drive_Is_Enabled)MUL(Master_Axis_Velocity,Conversion_Constant,axis_follower_velocity)COP(axis_follower_velocity,command_data_block[4],2);
   // The ramp acceleration is used to go from rest to motion.
   5: XIC(Axis_Input_Data.Drive_Is_Enabled)XIC(Axis_Input_Data.Stopped)MOV(Ramp_Acceleration,command_data_block[6]);
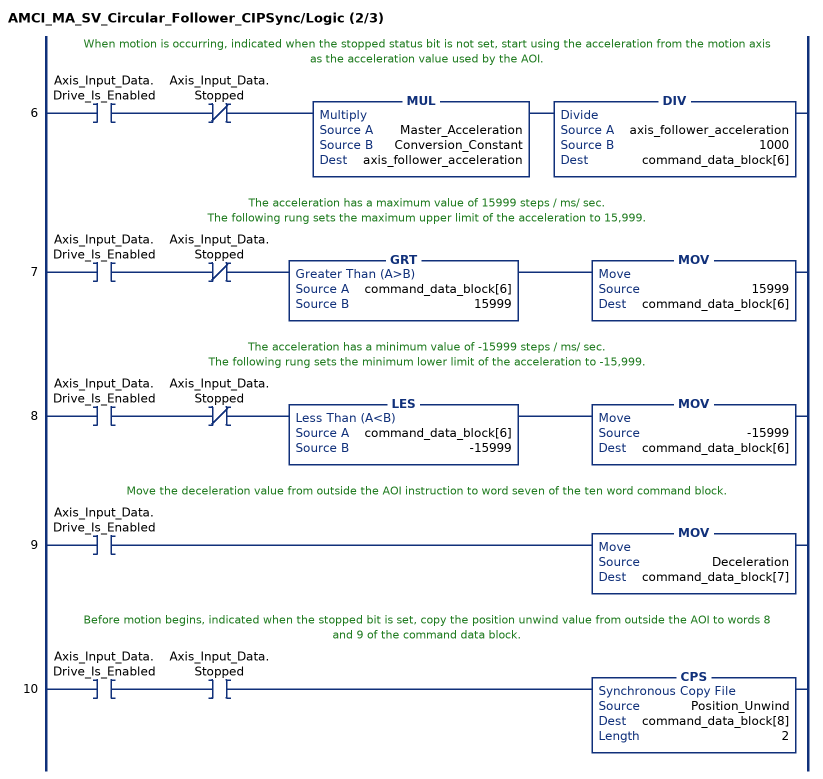
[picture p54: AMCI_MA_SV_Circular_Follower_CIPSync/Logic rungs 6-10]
   // When motion is occurring, indicated when the stopped status bit is not set, start using the acceleration from the motion axis as the acceleration value used by the AOI.
   6: XIC(Axis_Input_Data.Drive_Is_Enabled)XIO(Axis_Input_Data.Stopped)MUL(Master_Acceleration,Conversion_Constant,axis_follower_acceleration)DIV(axis_follower_acceleration,1000,command_data_block[6]);
   // The acceleration has a maximum value of 15999 steps / ms/ sec.
   // The following rung sets the maximum upper limit of the acceleration to 15,999.
   7: XIC(Axis_Input_Data.Drive_Is_Enabled)XIO(Axis_Input_Data.Stopped)GRT(command_data_block[6],15999)MOV(15999,command_data_block[6]);
   // The acceleration has a minimum value of -15999 steps / ms/ sec.
   // The following rung sets the minimum lower limit of the acceleration to -15,999.
   8: XIC(Axis_Input_Data.Drive_Is_Enabled)XIO(Axis_Input_Data.Stopped)LES(command_data_block[6],-15999)MOV(-15999,command_data_block[6]);
   // Move the deceleration value from outside the AOI instruction to word seven of the ten word command block.
   9: XIC(Axis_Input_Data.Drive_Is_Enabled)MOV(Deceleration,command_data_block[7]);
   // Before motion begins, indicated when the stopped bit is set, copy the position unwind value from outside the AOI to words 8 and 9 of the command data block.
   10: XIC(Axis_Input_Data.Drive_Is_Enabled)XIC(Axis_Input_Data.Stopped)CPS(Position_Unwind,command_data_block[8],2);
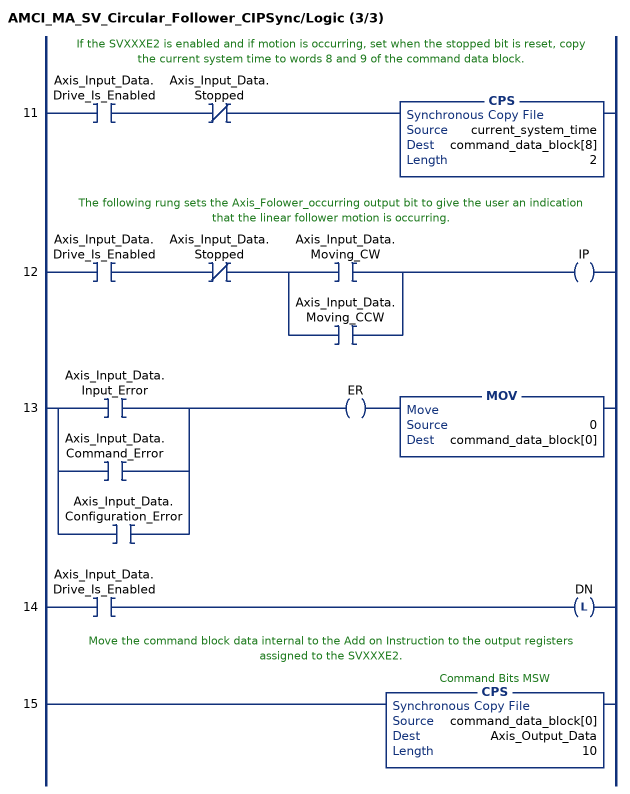
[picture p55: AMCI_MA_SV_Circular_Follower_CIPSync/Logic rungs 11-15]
   // If the SVXXXE2 is enabled and if motion is occurring, set when the stopped bit is reset, copy the current system time to words 8 and 9 of the command data block.
   11: XIC(Axis_Input_Data.Drive_Is_Enabled)XIO(Axis_Input_Data.Stopped)CPS(current_system_time,command_data_block[8],2);
   // The following rung sets the Axis_Folower_occurring output bit to give the user an indication that the linear follower motion is occurring.
   12: XIC(Axis_Input_Data.Drive_Is_Enabled)XIO(Axis_Input_Data.Stopped)[XIC(Axis_Input_Data.Moving_CW) ,XIC(Axis_Input_Data.Moving_CCW) ]OTE(IP);
   13: [XIC(Axis_Input_Data.Input_Error) ,XIC(Axis_Input_Data.Command_Error) ,XIC(Axis_Input_Data.Configuration_Error) ]OTE(ER)MOV(0,command_data_block[0]);
   14: XIC(Axis_Input_Data.Drive_Is_Enabled)OTL(DN);
   // Move the command block data internal to the Add on Instruction to the output registers assigned to the SVXXXE2.
   15: CPS(command_data_block[0],Axis_Output_Data,10);
END_ROUTINE
END_ADD_ON_INSTRUCTION
